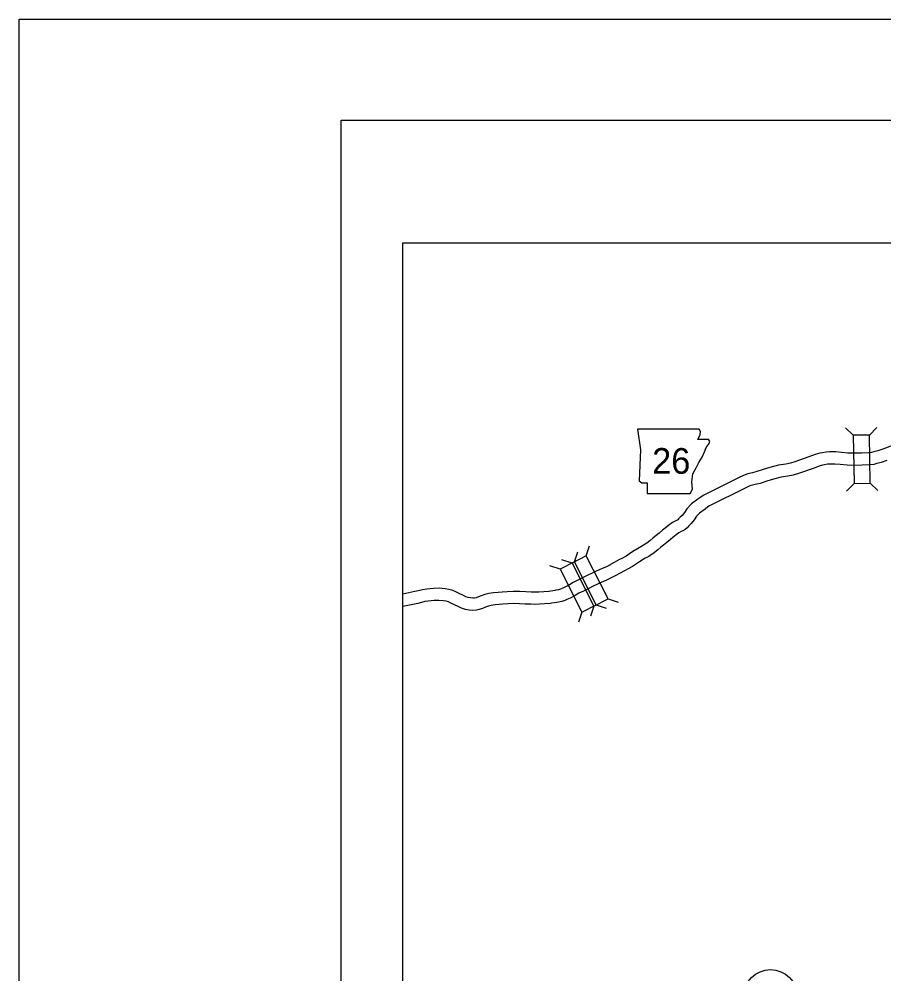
# Model space of a CAD drawing. Extents: x 1369979 to 1371646, y 379997 to 381064.
# Drawn here: x 1369978.9 to 1370145.5, y 380880.1 to 381064.1 of the extents above; entities that cross this region are included whole.
import ezdxf

# ---------------------------------------------------------------- set-up
doc = ezdxf.new("R2010")
doc.units = 0
for name, color, linetype in [('R_Border', 7, 'Continuous'), ('R_Border Notes', 7, 'Continuous'), ('R_No Plot', 7, 'Continuous')]:
    doc.layers.add(name, color=color, linetype=linetype)

msp = doc.modelspace()

# ---------------------------------------------------------------- linework, layer by layer
at = {"layer": 'R_Border'}
for p, q in [((1370040.95, 381044.6), (1371621.85, 381044.6)), ((1370040.95, 380017.3), (1370040.95, 381044.6))]:
    msp.add_line(p, q, dxfattribs=at)
at = {"layer": 'R_Border Notes'}
for p, q in [((1370139.59, 380983.89), (1370138.11, 380985.32)), ((1370142.69, 380983.93), (1370144.12, 380985.41)), ((1370139.73, 380974.61), (1370138.29, 380973.13)), ((1370142.82, 380974.65), (1370144.3, 380973.22)), ((1370085.87, 380959.5), (1370086.52, 380961.46)), ((1370088.16, 380960.66), (1370088.81, 380962.62)), ((1370085.41, 380959.26), (1370083.45, 380959.9)), ((1370083.11, 380958.11), (1370081.15, 380958.76)), ((1370092.7, 380958.91), (1370092.73, 380958.92)), ((1370093.85, 380956.87), (1370093.82, 380956.85)), ((1370092.36, 380952.38), (1370094.32, 380951.74)), ((1370089.6, 380950.98), (1370088.96, 380949.02)), ((1370090.04, 380951.21), (1370092, 380950.56)), ((1370087.28, 380949.82), (1370086.63, 380947.86))]:
    msp.add_line(p, q, dxfattribs=at)
for points in [[(1370098.02, 380985.06), (1370098.62, 380981.1), (1370098.35, 380975.09), (1370098.88, 380974.75), (1370099.87, 380974.75), (1370099.87, 380972.64), (1370108.2, 380972.64), (1370108.6, 380973.5), (1370108.46, 380974.89), (1370108.66, 380976.47), (1370109.39, 380977.73), (1370109.85, 380978.65), (1370110.51, 380979.65), (1370110.91, 380980.7), (1370111.24, 380981.56), (1370111.83, 380982.29), (1370111.97, 380982.75), (1370111.7, 380983.08), (1370109.65, 380983.08), (1370110.12, 380984.01), (1370110.18, 380984.6), (1370109.91, 380985.06)], [(1370139.59, 380983.89), (1370139.73, 380974.61), (1370142.82, 380974.65), (1370142.69, 380983.93)], [(1370090.04, 380951.21), (1370085.87, 380959.5), (1370083.11, 380958.11), (1370087.28, 380949.82)], [(1370085.41, 380959.26), (1370089.6, 380950.98), (1370092.36, 380952.38), (1370088.16, 380960.66)]]:
    msp.add_lwpolyline(points, close=True, dxfattribs=at)
for points in [[(1370147.16, 380981.89), (1370145.3, 380981.24), (1370144.29, 380980.91), (1370143.53, 380980.7), (1370143.09, 380980.59), (1370142.58, 380980.51), (1370141.2, 380980.44), (1370139.77, 380980.42), (1370138.52, 380980.44), (1370137.31, 380980.56), (1370136.2, 380980.69), (1370135.03, 380980.7), (1370134.35, 380980.65), (1370133.63, 380980.53), (1370133.15, 380980.44), (1370132.25, 380980.19), (1370131.03, 380979.72), (1370128.33, 380978.75), (1370127.5, 380978.52), (1370126.57, 380978.35), (1370125.17, 380978.14), (1370123.53, 380977.67), (1370122.25, 380977.27), (1370121.01, 380976.88), (1370120.16, 380976.67), (1370119.3, 380976.49), (1370118.75, 380976.3), (1370117.71, 380975.79), (1370110.69, 380972.3), (1370110.23, 380971.99), (1370109.66, 380971.55), (1370108.45, 380970.69), (1370107.53, 380969.74), (1370107.05, 380968.98), (1370106.6, 380968.43), (1370106.27, 380968.08), (1370105.95, 380967.76), (1370105.81, 380967.63), (1370105.65, 380967.54), (1370105.38, 380967.41), (1370104.77, 380967.1), (1370104.04, 380966.57), (1370103.36, 380966.02), (1370102.85, 380965.61), (1370102.18, 380965.03), (1370101.59, 380964.59), (1370101.03, 380964.16), (1370100.39, 380963.58), (1370099.85, 380963.12), (1370099.2, 380962.7)], [(1370146.05, 380979.01), (1370144.96, 380978.66), (1370144.11, 380978.43), (1370143.55, 380978.29), (1370142.82, 380978.18), (1370141.28, 380978.1), (1370139.76, 380978.08), (1370138.38, 380978.1), (1370137.06, 380978.23), (1370136.05, 380978.34), (1370135.1, 380978.35), (1370134.62, 380978.32), (1370134.04, 380978.22), (1370133.68, 380978.16), (1370132.99, 380977.96), (1370131.85, 380977.52), (1370129.05, 380976.52), (1370128.03, 380976.23), (1370126.96, 380976.03), (1370125.67, 380975.84), (1370124.21, 380975.43), (1370122.95, 380975.03), (1370121.64, 380974.62), (1370120.67, 380974.39), (1370119.93, 380974.23), (1370119.66, 380974.14), (1370118.76, 380973.69), (1370111.87, 380970.27), (1370111.6, 380970.09), (1370111.05, 380969.66), (1370109.98, 380968.9), (1370109.38, 380968.28), (1370108.96, 380967.61), (1370108.36, 380966.88), (1370107.94, 380966.44), (1370107.56, 380966.07), (1370107.19, 380965.72), (1370106.76, 380965.48), (1370106.45, 380965.32), (1370105.99, 380965.09), (1370105.47, 380964.71), (1370104.83, 380964.2), (1370104.36, 380963.81), (1370103.65, 380963.2), (1370103.01, 380962.72), (1370102.53, 380962.36), (1370101.93, 380961.82), (1370101.25, 380961.24), (1370100.76, 380960.92)], [(1370099.2, 380962.7), (1370099, 380962.58), (1370098.36, 380962.23), (1370097.13, 380961.51), (1370095.82, 380960.6), (1370095.12, 380960.23), (1370094.4, 380959.86), (1370093.51, 380959.37), (1370092.7, 380958.91)], [(1370100.73, 380960.9), (1370100.19, 380960.56), (1370099.51, 380960.19), (1370098.39, 380959.53), (1370097.04, 380958.6), (1370096.2, 380958.15), (1370095.5, 380957.79), (1370094.66, 380957.32), (1370093.85, 380956.87)], [(1370092.73, 380958.92), (1370092.16, 380958.62), (1370091.08, 380958.14), (1370090.08, 380957.69), (1370089.32, 380957.35), (1370088.45, 380956.91), (1370087.58, 380956.47), (1370086.55, 380955.96), (1370085.64, 380955.5), (1370084.9, 380955.08), (1370084.03, 380954.61), (1370083.52, 380954.39), (1370083.2, 380954.26), (1370082.82, 380954.13), (1370082.31, 380954.02)], [(1370093.82, 380956.85), (1370093.19, 380956.52), (1370092.04, 380956), (1370091.03, 380955.55), (1370090.32, 380955.23), (1370089.51, 380954.82), (1370088.63, 380954.38), (1370087.6, 380953.86), (1370086.75, 380953.44), (1370086.04, 380953.03), (1370085.04, 380952.49), (1370084.42, 380952.23), (1370084.04, 380952.07), (1370083.46, 380951.86), (1370082.84, 380951.74)], [(1370081.36, 380953.87), (1370080.93, 380953.81), (1370079.96, 380953.74), (1370079.05, 380953.69), (1370078.32, 380953.65), (1370077.57, 380953.68), (1370076.49, 380953.7), (1370075.39, 380953.78), (1370074.08, 380953.79), (1370072.95, 380953.75), (1370071.94, 380953.66), (1370071.16, 380953.62), (1370070.32, 380953.52), (1370069.42, 380953.4), (1370068.64, 380953.2), (1370067.94, 380952.95), (1370067.39, 380952.74), (1370066.92, 380952.6), (1370066.64, 380952.53), (1370066.31, 380952.5), (1370065.86, 380952.55), (1370065.43, 380952.61), (1370064.99, 380952.77), (1370064.49, 380953), (1370063.83, 380953.34), (1370063.06, 380953.7), (1370062.43, 380953.99), (1370061.7, 380954.19), (1370060.97, 380954.32), (1370059.84, 380954.42), (1370058.73, 380954.37), (1370057.44, 380954.25), (1370056.59, 380954.14), (1370055.79, 380953.93), (1370055.16, 380953.76), (1370052.8, 380953.26)], [(1370082.31, 380954.02), (1370082.09, 380953.97), (1370081.36, 380953.87)], [(1370081.47, 380951.52), (1370081.18, 380951.48), (1370080.11, 380951.4), (1370079.17, 380951.35), (1370078.33, 380951.31), (1370077.51, 380951.34), (1370076.39, 380951.36), (1370075.29, 380951.44), (1370074.12, 380951.45), (1370073.09, 380951.41), (1370072.1, 380951.32), (1370071.37, 380951.28), (1370070.61, 380951.19), (1370069.86, 380951.1), (1370069.33, 380950.96), (1370068.75, 380950.75), (1370068.15, 380950.52), (1370067.52, 380950.33), (1370067.03, 380950.22), (1370066.3, 380950.14), (1370065.57, 380950.22), (1370064.87, 380950.32), (1370064.11, 380950.59), (1370063.46, 380950.89), (1370062.8, 380951.23), (1370062.07, 380951.57), (1370061.62, 380951.78), (1370061.18, 380951.9), (1370060.65, 380952), (1370059.79, 380952.07), (1370058.89, 380952.03), (1370057.7, 380951.92), (1370057.05, 380951.84), (1370056.4, 380951.66), (1370055.7, 380951.48), (1370052.8, 380950.87)], [(1370082.84, 380951.74), (1370082.49, 380951.66), (1370081.47, 380951.52)]]:
    msp.add_lwpolyline(points, dxfattribs=at)
msp.add_circle((1370123.64, 380875.77), 5.16, dxfattribs=at)
at = {"layer": 'R_No Plot'}
msp.add_line((1369978.95, 381064.07), (1371645.61, 381064.07), dxfattribs=at)
for points in [[(1369978.91, 381064.07), (1371645.61, 381064.07), (1371645.61, 379997.39), (1369978.91, 379997.39)], [(1370052.8, 381020.95), (1370474.58, 381020.95), (1370474.58, 380650.53), (1370052.8, 380650.53)]]:
    msp.add_lwpolyline(points, close=True, dxfattribs=at)

# ---------------------------------------------------------------- texts
at = {"layer": 'R_Border Notes'}
msp.add_text('26', height=4.95, dxfattribs=at).set_placement((1370100.84, 380976.47))

doc.saveas('drawing.dxf')
